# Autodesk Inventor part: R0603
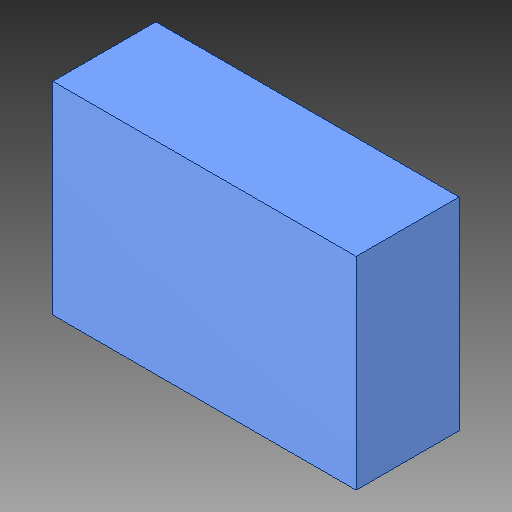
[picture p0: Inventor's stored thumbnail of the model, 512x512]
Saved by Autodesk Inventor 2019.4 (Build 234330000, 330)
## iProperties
Created: 2019-11
Part Number: R0603
Material: Generic
Document SubType Name: Modeling
Designer: Willist
Density: 1 g/cm^3
Appearance: R0603, R0603
Author: Willist
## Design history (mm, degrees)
sketch "R0603, R0603_79"
  geometry: L1 (-1.473, 0.983)-(1.473, 0.983); L2 (1.473, 0.983)-(1.473, -0.983); L3 (1.473, -0.983)-(-1.473, -0.983); L4 (-1.473, -0.983)-(-1.473, 0.983)
  constraints: 8 end point
extrude "Extrusion1" join sketch "R0603, R0603_79" distance "d0" = 1; taper "d1" = 0 deg
body "Solid1"
